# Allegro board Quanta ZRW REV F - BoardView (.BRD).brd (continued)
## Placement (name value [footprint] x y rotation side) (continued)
R257  *10k_4  [RC0402]  167.22 91.05 0 top
R258  75/f_6  [RC0603]  18.25 89.91 0 top
R259  ioac@10k_4  [RC0402]  46.32 87.75 0 top
R260  *ioac@100k/j_4  [RC0402]  48.35 87.75 0 top
R261  *15k_4  [RC0402]  41.11 87.24 180 top
R262  75/f_6  [RC0603]  18.25 86.99 0 top
R263  ioac@0_4  [RC0402]  45.68 86.61 0 top
R264  nac@0_4  [RC0402]  45.68 85.59 0 top
R265  *0_4  [RC0402]  175.09 85.11 0 top
R266  0_4  [RC0402]  210.91 85.57 0 top
R267  *0_4  [RC0402]  188.3 84.2 180 top
R268  *0_4  [RC0402]  175.09 84.1 0 top
R269  75/f_6  [RC0603]  18.25 83.94 0 top
R270  *0_4  [RC0402]  210.91 83.64 0 top
R271  *0_6  [RC0603]  170.52 83.05 90 top
R272  *0_6  [RC0603]  171.79 83.05 90 top
R273  *0_4  [RC0402]  175.09 82.83 0 top
R274  *0_4  [RC0402]  175.09 81.81 0 top
R275  *49.9k/f_4  [RC0402]  151.9 87.65 0 top
R276  *0/j_4  [RC0402]  36.92 81.4 90 top
R277  10k/f_4  [RC0402]  38.06 81.4 270 top
R278  *0_6  [RC0603]  171.92 80.89 0 top
R279  *0_4  [RC0402]  175.09 80.79 0 top
R280  *49.9k/f_4  [RC0402]  151.9 86.64 0 top
R281  *10k/f_4  [RC0402]  37.55 79.75 0 top
R282  *0_4  [RC0402]  175.22 79.5 0 top
R283  *49.9k/f_4  [RC0402]  158.97 79.37 180 top
R284  sp@0_4  [RC0402]  202.15 79.37 270 top
R285  *sp@0_4  [RC0402]  203.16 79.37 90 top
R286  *0_4  [RC0402]  204.18 79.37 270 top
R287  sp@0_4  [RC0402]  205.19 79.37 90 top
R288  *0_4  [RC0402]  206.21 79.37 90 top
R289  *0_6  [RC0603]  174.97 78.25 180 top
R290  *49.9k/f_4  [RC0402]  158.97 78.23 180 top
R291  *0_6  [RC0603]  174.97 76.98 180 top
R292  *4.7k_4  [RC0402]  22.82 76.45 90 top
R293  *4.7k_4  [RC0402]  23.84 76.45 90 top
R294  4.99k_4  [RC0402]  21.81 73.91 90 top
R295  *4.7k_4  [RC0402]  22.82 73.91 270 top
R296  *4.7k_4  [RC0402]  23.84 73.91 270 top
R297  4.7k_4  [RC0402]  24.85 73.91 90 top
R298  *4.7k_4  [RC0402]  25.87 73.91 90 top
R299  20k/f_4  [RC0402]  83.27 73.91 0 top
R300  20k/f_4  [RC0402]  85.31 73.91 180 top
R301  45.3k/f_4  [RC0402]  81.5 73.53 90 top
R302  *short_6  [SHORT0603]  93.56 73.02 270 top
R303  *120/f_4  [RC0402]  15.07 71.88 270 top
R304  1.5k/f_4  [RC0402]  81.5 71.5 90 top
R305  10k_4  [RC0402]  164.43 70.84 0 top
R306  *0_4  [RC0402]  29.68 70.48 180 top
R307  2/f_6  [RC0603]  93.87 70.38 90 top
R308  1k_4  [RC0402]  84.67 70.35 180 top
R309  1.8k/f_4  [RC0402]  95.47 70.33 270 top
R310  1.8k/f_4  [RC0402]  97.5 70.33 90 top
R311  *4.7k_4  [RC0402]  18.63 69.85 180 top
R312  *120/f_4  [RC0402]  15.07 69.59 270 top
R313  24.9/f_4  [RC0402]  94.3 68.45 0 top
R314  *120/f_4  [RC0402]  15.07 67.31 270 top
R315  *120/f_4  [RC0402]  15.07 64.89 270 top
R316  2.2k_4  [RC0402]  21.68 62.99 270 top
R317  2.2k_4  [RC0402]  22.69 62.99 270 top
R318  *shortgs@0_6  [SHORT0603]  204.81 62.73 90 top
R319  *2.2k_4  [RC0402]  29.55 62.61 180 top
R320  *4.7k_4  [RC0402]  23.71 62.23 90 top
R321  *4.7k_4  [RC0402]  24.73 62.23 270 top
R322  *2.2k_4  [RC0402]  29.55 61.46 180 top
R323  10k_4  [RC0402]  162.9 60.85 90 top
R324  *10k_4  [RC0402]  164 60.85 270 top
R325  24.9/f_4  [RC0402]  94.58 60.32 180 top
R326  *0_4  [RC0402]  223.99 59.46 180 top
R327  *short_6  [SHORT0603]  92.16 58.8 270 top
R328  2/f_6  [RC0603]  92.16 56 90 top
R329  *shortgs@0_4  [SHORT0402]  197.83 55.8 0 top
R330  1.8k/f_4  [RC0402]  93.31 55.75 270 top
R331  1.8k/f_4  [RC0402]  95.34 55.75 90 top
R332  10k_4  [RC0402]  162.01 55.34 90 top
R333  *4.7k_4  [RC0402]  197.83 54.61 0 top
R334  *4.7k_4  [RC0402]  199.48 52.57 0 top
R335  10k_4  [RC0402]  163.54 52.35 90 top
R336  *shortgs@0_4  [SHORT0402]  201 52.07 90 top
R337  *shortgs@0_4  [SHORT0402]  203.54 52.07 90 top
R338  *short_6  [SHORT0603]  36.92 51.3 270 top
R339  *short_8  [SHORT0805]  221.32 51.3 90 top
R340  *short_4  [SHORT0402]  24.09 50.54 0 top
R341  *short_4  [SHORT0402]  24.09 49.53 0 top
R342  *short_4  [SHORT0402]  22.57 48.26 0 top
R343  *100k_4  [RC0402]  29.81 48.13 0 top
R344  *0_4  [RC0402]  31.97 48.13 0 top
R345  *1m_6  [RC0603]  34.51 48 0 top
R346  1.8k/f_4  [RC0402]  142.79 47.75 0 top
R347  *10k_4  [RC0402]  162.85 47.62 0 top
R348  *short_4  [SHORT0402]  22.57 47.24 0 top
R349  33_4  [RC0402]  179.59 121.64 270 top
R350  0_4  [RC0402]  31.97 47.11 180 top
R351  *0_4  [RC0402]  224.37 46.99 180 top
R352  22k_4  [RC0402]  36.03 46.86 180 top
R353  *short_4  [SHORT0402]  22.57 46.22 0 top
R354  4.7k_4  [RC0402]  36.03 45.72 0 top
R355  *short_4  [SHORT0402]  22.57 45.21 0 top
R356  10k_4  [RC0402]  26.76 44.7 0 top
R357  24.9/f_4  [RC0402]  136.74 44.07 180 top
R358  1.8k/f_4  [RC0402]  141.06 44.07 0 top
R359  33_4  [RC0402]  38.82 43.94 180 top
R360  10k_4  [RC0402]  26.76 43.56 0 top
R361  *2.2_6  [RC0603]  209.66 43.25 90 top
R362  *short_6  [SHORT0603]  138.14 42.97 0 top
R363  2/f_6  [RC0603]  140.8 42.97 180 top
R364  100k_4  [RC0402]  24.22 42.41 90 top
R365  0_4  [RC0402]  26.25 41.91 270 top
R366  *0_4  [RC0402]  27.27 41.91 270 top
R367  *short_6  [SHORT0603]  40.35 41.4 270 top
R368  100k_4  [RC0402]  205.32 40.51 270 top
R369  *10k/j_4  [RC0402]  40.86 38.98 270 top
R370  22_4  [RC0402]  34.76 38.86 0 top
R371  *short_4  [SHORT0402]  36.92 38.86 180 top
R372  1k_4  [RC0402]  39.84 38.86 90 top
R373  *22_4  [RC0402]  207.99 38.6 180 top
R374  10k_4  [RC0402]  205.32 38.35 270 top
R375  *0_4  [RC0402]  26.38 37.33 0 top
R376  39k/f_4  [RC0402]  19.9 37.03 270 top
R377  20k/f_4  [RC0402]  20.92 37.03 90 top
R378  100k_4  [RC0402]  26.38 36.32 180 top
R379  ev@10k_4  [RC0402]  205.32 36.32 270 top
R380  100k_4  [RC0402]  207.23 35.81 180 top
R381  *short_4  [SHORT0402]  19.77 35.05 0 top
R382  ev@10k_4  [RC0402]  196.1 34.62 180 top
R383  200k_4  [RC0402]  26.89 34.54 270 top
R384  *short_4  [SHORT0402]  19.77 34.03 0 top
R385  *short_4  [SHORT0402]  19.14 32.76 0 top
R386  *short_4  [SHORT0402]  19.14 31.75 0 top
R387  *short_4  [SHORT0402]  19.14 30.6 0 top
R388  *short_6  [SHORT0603]  25.87 30.6 180 top
R389  100k_4  [RC0402]  208.19 30.77 90 top
R390  *10k/f_4  [RC0402]  42.13 29.97 180 top
R391  *short_6  [SHORT0603]  57.62 29.97 180 top
R392  *short_4  [SHORT0402]  19.14 29.59 0 top
R393  *0_4  [RC0402]  21.55 29.03 270 top
R394  *0_4  [RC0402]  23.18 29 270 top
R395  *29.4k/f_4  [RC0402]  42.13 28.95 180 top
R396  *0_4  [RC0402]  53.94 28.44 270 top
R397  100k_4  [RC0402]  29.93 28.06 270 top
R398  6.2k/f_4  [RC0402]  60.54 28.06 270 top
R399  *0_4  [RC0402]  15.07 26.67 270 top
R400  *0_4  [RC0402]  16.09 26.67 270 top
R401  *0_4  [RC0402]  35.52 26.46 270 top
R402  *short_4  [SHORT0402]  202.15 24.76 180 top
R403  *tdi@0_4  [RC0402]  201.13 23.24 0 top
R404  *short_6  [SHORT0603]  60.28 16.35 0 top
R405  *tdi@0_4  [RC0402]  201.13 21.97 180 top
R406  *short_6  [SHORT0603]  62.69 17.14 270 top
R407  2.2k/j_4  [RC0402]  18.45 20.38 90 top
R408  *short_4  [SHORT0402]  16.93 20.34 180 top
R409  2.2k_4  [RC0402]  207.07 20.14 90 top
R410  2.2k_4  [RC0402]  208.14 20.11 90 top
R411  *short_4  [SHORT0402]  203.42 19.68 90 top
R412  *short_4  [SHORT0402]  204.56 19.68 90 top
R413  *short_4  [SHORT0402]  58 18.54 90 top
R414  *short_6  [SHORT0603]  64.95 17.14 270 top
R415  10k_4  [RC0402]  203.42 17.52 270 top
R416  10k_4  [RC0402]  204.56 17.52 270 top
R417  *10k/j_4  [RC0402]  15.33 17.01 270 top
R418  4.7k_4  [RC0402]  19.52 17.01 270 top
R419  *short_6  [SHORT0603]  67.22 17.16 270 top
R420  62/f_4  [RC0402]  14.7 15.36 180 top
R421  4.7k_4  [RC0402]  18.96 14.22 270 top
R422  62/f_4  [RC0402]  15.1 13.7 90 top
R423  *10k/j_4  [RC0402]  16.12 13.7 270 top
R424  2.2k/j_4  [RC0402]  18.96 12.1 90 top
R425  *short_4  [SHORT0402]  17.31 11.71 180 top
R426  *1m_4  [RC0402]  59.27 11.55 270 top
R427  *1m_4  [RC0402]  60.41 11.55 270 top
R428  *1m_4  [RC0402]  67.4 11.55 270 top
R429  *1m_4  [RC0402]  68.54 11.55 270 top
R430  71.5/f_4  [RC0402]  67.4 9.52 90 top
R431  130/f_4  [RC0402]  68.54 9.52 90 top
R432  71.5/f_4  [RC0402]  59.27 9.39 90 top
R433  130/f_4  [RC0402]  60.41 9.39 90 top
R434  *short_6  [SHORT0603]  63.84 8.76 270 top
R435  *100k_4  [RC0402]  64.99 8.5 270 top
R436  *1m_4  [RC0402]  57.49 7.74 270 top
R437  *short_4  [SHORT0402]  67.02 5.84 180 top
R438  *short_4  [SHORT0402]  59.27 5.71 180 top
R439  *0_4  [RC0402]  67.02 4.82 0 top
R440  *0_4  [RC0402]  59.27 4.69 0 top
R441  33_4  [RC0402]  146.77 196.44 0 bottom
R442  *short_4  [SHORT0402]  143.6 193.42 90 bottom
R443  *0_4  [RC0402]  144.61 193.42 270 bottom
R444  *tsi@10k_4  [RC0402]  135.98 184.65 180 bottom
R445  ev@100/f_4  [RC0402]  199.86 190.75 0 bottom
R446  ev@100/f_4  [RC0402]  202.02 190.75 180 bottom
R447  *100k_4  [RC0402]  138.39 188.34 180 bottom
R448  *100k_4  [RC0402]  138.39 187.32 0 bottom
R449  *100k_4  [RC0402]  138.39 190.37 0 bottom
R450  *100k_4  [RC0402]  138.39 189.35 180 bottom
R451  ev@100/f_4  [RC0402]  199.86 189.35 0 bottom
R452  ev@100/f_4  [RC0402]  202.02 189.35 180 bottom
R453  ev@10k/f_4  [RC0402]  196.43 188.97 0 bottom
R455  ev@100/f_4  [RC0402]  199.86 188.21 0 bottom
R456  ev@100/f_4  [RC0402]  202.02 188.21 180 bottom
R457  33_4  [RC0402]  138.14 186.3 180 bottom
R458  ev@100/f_4  [RC0402]  200.88 186.94 0 bottom
R459  ev@100/f_4  [RC0402]  203.03 186.94 180 bottom
R460  33_4  [RC0402]  113.37 181.73 90 top
R461  ev@100/f_4  [RC0402]  200.88 185.8 0 bottom
R462  ev@100/f_4  [RC0402]  203.03 185.8 180 bottom
R463  100k_4  [RC0402]  196.1 35.68 180 top
R464  ev@243_4  [RC0402]  194.02 184.58 270 bottom
R465  1k_4  [RC0402]  155.16 184.15 0 bottom
R466  ev@1.33k/f_4  [RC0402]  203.16 181.35 270 bottom
R467  ev@1.33k/f_4  [RC0402]  168.11 180.18 270 bottom
R469  ev@1.33k/f_4  [RC0402]  203.54 178.43 180 bottom
R471  ev@243_4  [RC0402]  177.89 172.33 0 bottom
R472  ev@1.33k/f_4  [RC0402]  169.3 171.93 270 bottom
R473  ev@2.49k/f_4  [RC0402]  168.11 167.13 90 bottom
R478  *0_4  [RC0402]  165.87 164.56 90 bottom
R481  *200/f_4  [RC0402]  168.03 164.26 90 bottom
R485  10k_4  [RC0402]  164.93 161.67 0 bottom
R486  ev@243_4  [RC0402]  207.99 156.71 90 bottom
R487  ev@243_4  [RC0402]  219.8 156.59 90 bottom
R488  *1k_4  [RC0402]  161.89 155.06 0 bottom
R489  *10k/f_4  [RC0402]  164.82 148.88 270 bottom
R490  ev@10k/f_4  [RC0402]  165.96 148.88 90 bottom
R491  gt@4.99k/f_4  [RC0402]  208.08 147.79 180 bottom
R492  gt@4.99k/f_4  [RC0402]  203.87 147.77 180 bottom
R493  sp@30.1k/f_4  [RC0402]  205.96 147.77 0 bottom
R494  gm@4.99k/f_4  [RC0402]  208.08 146.77 0 bottom
R495  gm@4.99k/f_4  [RC0402]  203.87 146.76 0 bottom
R496  *sp@4.99k/f_4  [RC0402]  206.01 146.76 180 bottom
R497  *10k/f_4  [RC0402]  166.05 146.73 90 bottom
R498  *10k/f_4  [RC0402]  164.79 146.72 270 bottom
R499  *10k/f_4  [RC0402]  185.27 141.26 90 bottom
R500  *10k/f_4  [RC0402]  187.55 141.26 90 bottom
R501  ev@10k/f_4  [RC0402]  189.84 141.26 90 bottom
R502  ev@1.8k_4  [RC0402]  193.27 141.26 90 bottom
R503  ev@2.2k_4  [RC0402]  194.41 141.26 90 bottom
R504  ev@10k/f_4  [RC0402]  195.55 141.26 90 bottom
R505  ev@2.2k_4  [RC0402]  196.7 141.26 270 bottom
R506  *10k/f_4  [RC0402]  183.98 141.22 90 bottom
R507  sp@49.9k/f_4  [RC0402]  186.4 141.22 270 bottom
R508  gm@10k/f_4  [RC0402]  188.81 141.22 270 bottom
R509  *10k/f_4  [RC0402]  180.3 141.14 90 bottom
R510  ev@40.2k/f_4  [RC0402]  181.57 141.14 270 bottom
R511  ev@10k/f_4  [RC0402]  182.74 141.12 90 bottom
R512  2.7k/f_4  [RC0402]  125.82 140.46 270 bottom
R513  *1k_4  [RC0402]  121.12 140.33 0 bottom
R514  51_4  [RC0402]  123.02 140.08 90 bottom
R515  51_4  [RC0402]  124.04 140.08 90 bottom
R516  ev@10k/f_4  [RC0402]  190.97 139.47 90 bottom
R517  *short_4  [SHORT0402]  121.5 139.31 180 bottom
R518  ev@10k/f_4  [RC0402]  189.84 139.22 90 bottom
R519  gm@45.3k/f_4  [RC0402]  185.27 139.1 90 bottom
R520  gm@45.3k/f_4  [RC0402]  187.55 139.1 90 bottom
R521  ev@1.8k_4  [RC0402]  193.27 139.1 90 bottom
R522  ev@2.2k_4  [RC0402]  194.51 139.1 90 bottom
R523  ev@2.2k_4  [RC0402]  195.55 139.1 270 bottom
R524  ev@10k/f_4  [RC0402]  196.7 139.1 90 bottom
R525  ev@10k/f_4  [RC0402]  182.74 139.09 90 bottom
R526  gm@4.99k/f_4  [RC0402]  183.98 139.06 90 bottom
R527  *24.9k/f_4  [RC0402]  186.4 139.06 90 bottom
R528  *15k/f_4  [RC0402]  188.81 139.06 270 bottom
R529  1k_4  [RC0402]  119.04 143.1 0 bottom
R530  100/f_4  [RC0402]  117.51 143.49 90 bottom
R531  499/f_4  [RC0402]  112.33 133.07 180 bottom
R532  *100k_4  [RC0402]  115.4 137.79 270 bottom
R533  *100k_4  [RC0402]  116.42 137.79 90 bottom
R534  51_4  [RC0402]  120.74 137.79 90 bottom
R535  *51_4  [RC0402]  121.75 137.79 90 bottom
R536  1m_4  [RC0402]  134.45 137.79 270 bottom
R537  *51_4  [RC0402]  123.53 137.66 90 bottom
R538  51_4  [RC0402]  124.55 137.66 90 bottom
R539  *short_4  [SHORT0402]  125.56 137.66 90 bottom
R540  10k_4  [RC0402]  159.47 137.16 270 bottom
R541  10k_4  [RC0402]  158.84 139.19 180 bottom
R542  10k_4  [RC0402]  158.46 137.16 270 bottom
R543  10k_4  [RC0402]  155.92 141.73 270 bottom
R544  *10k_4  [RC0402]  111.26 131.93 180 bottom
R546  *0_4  [RC0402]  127.52 136.9 90 bottom
R548  1k_4  [RC0402]  112.81 129.51 270 bottom
R549  *short_4  [SHORT0402]  121.63 136.27 0 bottom
R550  *short_6  [SHORT0603]  148.17 136.65 270 bottom
R552  220_4  [RC0402]  113.75 138.68 270 bottom
R553  *0_4  [RC0402]  127.98 135.38 180 bottom
R554  10k_4  [RC0402]  112.81 131.54 90 bottom
R555  10k_4  [RC0402]  159.85 135.12 90 bottom
R556  *short_4  [SHORT0402]  160.87 135.12 270 bottom
R558  51_4  [RC0402]  120.74 134.74 90 bottom
R559  51_4  [RC0402]  121.75 134.74 90 bottom
R560  *short_4  [SHORT0402]  162.73 134.51 0 bottom
R561  10k_4  [RC0402]  167.35 133.85 0 bottom
R562  100/f_4  [RC0402]  160.11 131.69 90 bottom
R563  100k_4  [RC0402]  162.24 129.87 0 bottom
R564  100k_4  [RC0402]  163.79 131.95 90 bottom
R565  gt3@0_6  [RC0603]  107.96 131.67 0 bottom
R566  *10k_4  [RC0402]  161.51 131.69 270 bottom
R567  *short_4  [SHORT0402]  167.35 129.79 180 bottom
R568  10k_4  [RC0402]  172.07 127.02 270 bottom
R569  *10k_4  [RC0402]  163.92 129.54 270 bottom
R570  100k_4  [RC0402]  171.06 127.25 270 bottom
R571  *short_4  [SHORT0402]  167.35 128.77 180 bottom
R572  2.2k_4  [RC0402]  169.38 129.03 180 bottom
R573  *10k_4  [RC0402]  160.11 127.38 270 bottom
R574  *10k_4  [RC0402]  161.12 127.38 270 bottom
R575  *10k_4  [RC0402]  162.52 127.38 270 bottom
R576  2.2k_4  [RC0402]  169.38 127.76 180 bottom
R577  2.2k_4  [RC0402]  169.38 126.74 180 bottom
R578  2.2k_4  [RC0402]  166.2 125.09 180 bottom
R580  2.2k_4  [RC0402]  164.15 125.29 0 bottom
R582  2.2k_4  [RC0402]  167.73 124.58 270 bottom
R585  2.2k_4  [RC0402]  161 120.9 270 bottom
R586  *1k_4  [RC0402]  159.98 120.52 270 bottom
R587  1k_4  [RC0402]  163.44 116.73 90 bottom
R588  8m@15_4  [RC0402]  172.81 115.54 0 bottom
R589  8m4m@15_4  [RC0402]  175.6 115.67 180 bottom
R590  *10k_4  [RC0402]  164.05 115.19 180 bottom
R591  10k_4  [RC0402]  170.65 115.18 180 bottom
R592  10k_4  [RC0402]  162.01 115.19 0 bottom
R593  10k_4  [RC0402]  166.08 115.06 0 bottom
R594  *4m@33_4  [RC0402]  172.76 114.52 0 bottom
R595  10k_4  [RC0402]  166.08 114.04 0 bottom
R596  *4m@33_4  [RC0402]  174.94 114.02 90 bottom
R597  *1k_4  [RC0402]  175.96 114.02 90 bottom
R598  10k_4  [RC0402]  162.01 114.07 0 bottom
R599  *10k_4  [RC0402]  164.05 114.07 180 bottom
R600  *10k_4  [RC0402]  168.11 113.91 180 bottom
R601  2.2k_4  [RC0402]  11.52 113.66 90 bottom
R602  8m@0_4  [RC0402]  169.76 113.66 90 bottom
R603  *4m@0_4  [RC0402]  170.78 113.66 90 bottom
R604  *4m@33_4  [RC0402]  172.58 113.51 0 bottom
R605  10k_4  [RC0402]  166.08 112.9 0 bottom
R606  10k_4  [RC0402]  166.97 116.07 180 bottom
R607  *10k_4  [RC0402]  168.24 115.06 180 bottom
R608  *10k_4  [RC0402]  168.11 112.77 180 bottom
R609  10k_4  [RC0402]  68.03 110.1 270 top
R610  10k_4  [RC0402]  162.06 111.83 0 bottom
R611  *10k_4  [RC0402]  164.1 111.83 180 bottom
R612  10k_4  [RC0402]  166.18 111.76 0 bottom
R613  *10k_4  [RC0402]  168.21 111.76 180 bottom
R614  10k_4  [RC0402]  162.12 110.82 180 bottom
R615  *10k_4  [RC0402]  164.15 110.82 180 bottom
R616  200/f_4  [RC0402]  166.2 110.74 0 bottom
R617  *0_4  [RC0402]  168.24 110.74 180 bottom
R618  10k_4  [RC0402]  162.27 109.72 180 bottom
R619  *1k_4  [RC0402]  164.99 109.72 180 bottom
R620  2.2k_4  [RC0402]  11.52 109.22 90 bottom
R621  *10k_4  [RC0402]  112.36 108.4 0 bottom
R622  *0_4  [RC0402]  168.11 108.78 0 bottom
R623  22/j_4  [RC0402]  162.01 108.71 0 bottom
R624  *20k_4  [RC0402]  164.05 108.71 180 bottom
R625  *1k_4  [RC0402]  166.08 108.71 0 bottom
R626  22/j_4  [RC0402]  164.05 107.69 0 bottom
R627  22/j_4  [RC0402]  166.08 107.69 0 bottom
R628  8.2k/f_4  [RC0402]  169.25 106.88 0 bottom
R629  10k_4  [RC0402]  166.08 106.68 0 bottom
R630  8.2k/f_4  [RC0402]  160.97 106.55 0 bottom
R631  *10k_4  [RC0402]  164.05 106.55 180 bottom
R632  gt3@0_4  [RC0402]  89.75 103.37 180 bottom
R633  gt3@0_4  [RC0402]  89.75 104.39 180 bottom
R634  gt3@0_4  [RC0402]  87.72 104.39 0 bottom
R635  49.9/f_4  [RC0402]  167.73 105.41 0 bottom
R636  gt3@0_4  [RC0402]  87.72 103.37 0 bottom
R637  *short_6  [SHORT0603]  17.69 104.62 0 bottom
R639  10k_4  [RC0402]  156.68 104.52 270 bottom
R640  *short_4  [SHORT0402]  157.82 104.52 270 bottom
R641  *4m@33_4  [RC0402]  177.63 104.52 270 bottom
R642  10k_4  [RC0402]  153.63 104.39 90 bottom
R643  *0_4  [RC0402]  152.62 104.34 270 bottom
R644  33_4  [RC0402]  147.15 104.26 270 bottom
R645  33_4  [RC0402]  148.17 104.01 270 bottom
R646  49.9/f_4  [RC0402]  167.88 103.88 90 bottom
R647  *short_4  [SHORT0402]  150.58 103.63 270 bottom
R648  10k_4  [RC0402]  151.6 103.63 270 bottom
R649  1k_4  [RC0402]  170.9 102.87 90 bottom
R650  8m4m@15_4  [RC0402]  169.51 102.74 90 bottom
R651  8.2k/f_4  [RC0402]  155.16 102.48 90 bottom
R652  *short_4  [SHORT0402]  156.68 102.48 90 bottom
R653  *short_4  [SHORT0402]  157.82 102.48 270 bottom
R654  8m@15_4  [RC0402]  177.63 102.48 90 bottom
R655  *short_4  [SHORT0402]  153.63 102.23 90 bottom
R657  *short_8  [SHORT0805]  226.91 101.09 0 bottom
R658  *4m@33_4  [RC0402]  177.76 100.86 180 bottom
R659  *short_4  [SHORT0402]  157.82 100.5 270 bottom
R660  33_4  [RC0402]  149.95 100.2 270 bottom
R661  *short_4  [SHORT0402]  152.49 100.2 90 bottom
R667  33_4  [RC0402]  148.3 99.56 0 bottom
R668  *short_4  [SHORT0402]  167.22 99.41 270 bottom
R669  *4m@33_4  [RC0402]  177.38 99.31 180 bottom
R670  *short_4  [SHORT0402]  154.39 98.42 0 bottom
R671  nac@0_4  [RC0402]  191.86 98.17 0 bottom
R672  nac@0_8  [RC0805]  222.31 98.04 90 bottom
R673  ioac@22_8  [RC0805]  224.32 98.04 90 bottom
R674  *0_4  [RC0402]  151.85 97.91 90 bottom
R675  100k_4  [RC0402]  152.87 97.91 270 bottom
R676  *short_4  [SHORT0402]  156.55 97.84 90 bottom
R677  *short_4  [SHORT0402]  157.57 97.84 90 bottom
R678  80.6/f_4  [RC0402]  166.33 98.01 0 bottom
R679  470_4  [RC0402]  154.39 97.4 0 bottom
R680  ioac@0_4  [RC0402]  191.86 97.15 0 bottom
R681  100/f_4  [RC0402]  166.33 97 0 bottom
R682  *100k_4  [RC0402]  99.66 96.64 90 bottom
R683  *0_6  [RC0603]  164.1 95.86 180 bottom
R684  8m4m@15_4  [RC0402]  177.38 96.01 0 bottom
R685  120/f_4  [RC0402]  166.61 95.83 0 bottom
R686  ioac@100k  [RC0402]  216.24 95.5 0 bottom
R687  8m@15_4  [RC0402]  177.38 94.99 0 bottom
R688  *short_4  [SHORT0402]  191.86 94.1 180 bottom
R689  *4m@33_4  [RC0402]  177.38 93.98 180 bottom
R690  *short_4  [SHORT0402]  191.86 93.09 180 bottom
R691  8m4m@15_4  [RC0402]  177.51 92.96 180 bottom
R692  *ioac@100k  [RC0402]  215.86 92.32 0 bottom
R693  *short_4  [SHORT0402]  191.86 92.07 180 bottom
R694  *0_4  [RC0402]  177.51 91.82 0 bottom
R695  ioac@100k  [RC0402]  222.59 91.82 0 bottom
R696  *short_4  [SHORT0402]  191.99 91.05 180 bottom
R697  gt3@10k_4  [RC0402]  58.89 90.8 270 bottom
R698  1k_4  [RC0402]  171.67 90.8 0 bottom
R699  *0_4  [RC0402]  177.51 90.8 0 bottom
R700  *short_6  [SHORT0603]  169 89.78 0 bottom
R701  2.49k/f_4  [RC0402]  34.25 89.66 0 bottom
R702  ioac@10k/f_4  [RC0402]  45.55 89.66 180 bottom
R703  *ioac@0_4  [RC0402]  215.23 89.66 90 bottom
R704  ioac@0_4  [RC0402]  216.37 89.66 90 bottom
R705  gt3@10k_4  [RC0402]  54.83 88.77 270 bottom
R706  *10k_4  [RC0402]  55.84 88.77 90 bottom
R707  gt3@10k_4  [RC0402]  56.86 88.77 90 bottom
R708  *10k_4  [RC0402]  57.87 88.77 270 bottom
R709  nac@0/j_4  [RC0402]  48.6 88.26 90 bottom
R710  *ioac@10k_4  [RC0402]  178.14 87.63 270 bottom
R711  1k_4  [RC0402]  41.11 87.24 0 bottom
R712  **ioac@100k/j_4  [RC0402]  175.86 86.74 180 bottom
R713  nac@0_4  [RC0402]  49.24 86.74 180 bottom
R714  *10k_4  [RC0402]  194.27 86.23 0 bottom
R715  ioac@0_4  [RC0402]  49.24 85.72 180 bottom
R716  **10k_4  [RC0402]  193.76 82.67 0 bottom
R717  *10k_4  [RC0402]  218.53 77.08 180 bottom
R718  *0_4  [RC0402]  19.75 76.5 270 bottom
R719  100k_4  [RC0402]  211.8 75.81 0 bottom
R720  20k_4  [RC0402]  14.19 75.69 0 bottom
R721  0_4  [RC0402]  14.19 74.67 0 bottom
R722  *1m_4  [RC0402]  14.19 73.66 180 bottom
R723  tpm_i@0_6  [RC0603]  214.85 61.21 0 bottom
R724  *4.7k_4  [RC0402]  214.85 59.94 180 bottom
R725  tpm_n@0_6  [RC0603]  211.42 59.43 0 bottom
R726  tpm_i@0_4  [RC0402]  218.53 59.05 0 bottom
R727  tpm_i@4.7k_4  [RC0402]  214.59 58.42 90 bottom
R728  tpm_i@0_4  [RC0402]  215.73 58.42 90 bottom
R729  *10k_4  [RC0402]  216.88 58.42 90 bottom
R730  10k_4  [RC0402]  197.45 51.81 270 bottom
R731  4.7k_4  [RC0402]  198.59 51.81 270 bottom
R732  4.7k_4  [RC0402]  199.73 51.81 270 bottom
R733  2.2k_4  [RC0402]  200.88 51.81 270 bottom
R734  2.2k_4  [RC0402]  201.89 51.81 270 bottom
R735  *10k_4  [RC0402]  194.91 49.14 270 bottom
R736  *10k_4  [RC0402]  196.05 49.14 270 bottom
R737  1k_4  [RC0402]  198.46 49.14 270 bottom
R738  43_4  [RC0402]  201.79 49.14 270 bottom
R739  100k_4  [RC0402]  202.91 49.14 270 bottom
R740  ev@10k_4  [RC0402]  205.19 49.14 270 bottom
R741  10k_4  [RC0402]  193.64 49.02 270 bottom
R742  *short_4  [SHORT0402]  218.78 46.6 90 bottom
R743  tpm_n@0_4  [RC0402]  219.93 46.6 90 bottom
R744  *4.7k_4  [RC0402]  211.14 45.97 270 bottom
R745  *shorttpm@0_6  [SHORT0603]  212.43 45.72 270 bottom
R746  33_4  [RC0402]  227.8 112.14 0 top
R747  2.2_6  [RC0603]  188.81 44.7 90 bottom
R748  *0_4  [RC0402]  210.02 35.05 90 bottom
R749  *short_4  [SHORT0402]  211.7 34.51 180 bottom
R750  *short_4  [SHORT0402]  32.73 31.36 90 bottom
R751  33_4  [RC0402]  142.46 191.26 90 bottom
R752  *short_6  [SHORT0603]  203.29 26.16 90 bottom
R753  10k_4  [RC0402]  193.26 23.36 180 bottom
R754  *0_4  [RC0402]  208.88 23.11 0 bottom
R755  *0_4  [RC0402]  213.3 18.26 270 bottom
R756  *0_4  [RC0402]  216.5 77.59 0 bottom
R757  *0_4  [RC0402]  216.5 76.58 0 bottom
R758  *ev@0_4  [RC0402]  196.56 145.54 90 top
R759  *short_4  [SHORT0402]  160.01 110.89 90 bottom
R760  *short_4  [SHORT0402]  110.93 109.57 180 bottom
R761  100k_4  [RC0402]  110.96 137.16 0 bottom
R762  *gt3@0_4  [RC0402]  93.56 111.5 0 bottom
R764  10k_4  [RC0402]  160.87 116.53 0 top
R765  *10k_4  [RC0402]  163.39 118.21 270 top
R766  10k_4  [RC0402]  161.86 112.98 0 bottom
R767  *10k_4  [RC0402]  164.05 112.98 180 bottom
R768  *60.4/f_4  [RC0402]  126.23 140.81 180 top
R769  *33_4  [RC0402]  166.97 131.19 0 bottom
R770  *33_4  [RC0402]  166.97 132.2 0 bottom
R771  *0_4  [RC0402]  208.25 92.06 0 top
R772  *0_4  [RC0402]  210.52 85.18 270 top
R774  33_4  [RC0402]  191.86 96.13 0 bottom
R775  *0_4  [RC0402]  162.9 118.28 0 bottom
R776  33_4  [RC0402]  143.65 16.15 270 bottom
R777  *0_4  [RC0402]  197.47 85.82 270 top
R778  1k_4  [RC0402]  164 112.34 0 top
R779  2.2_6  [RC0603]  209.88 40.62 270 top
R780  20k/f_4  [RC0402]  169.87 131.33 270 bottom
R781  20k/f_4  [RC0402]  168.83 130.82 90 bottom
R782  0_4  [RC0402]  196.35 49.06 270 top
R783  *0_4  [RC0402]  188.73 42.34 270 bottom
R784  *0_4  [RC0402]  208.75 45.79 180 bottom
R785  *0_4  [RC0402]  210.53 33.5 180 bottom
R786  100k_4  [RC0402]  172.25 43.51 270 top
R787  *0_4  [RC0402]  214.31 17.95 90 bottom
R788  49.9/f_4  [RC0402]  119.04 142.08 0 bottom
R789  0_6  [RC0603]  163.41 97.02 180 bottom
R790  *0_4  [RC0402]  221.58 24.76 180 top
R791  0_4  [RC0402]  51.14 11.32 0 top
R792  *0_4  [RC0402]  51.14 15.19 0 top
R793  gt3@0_8  [RC0805]  65.49 96.26 180 bottom
R794  gt3@0_8  [RC0805]  65.49 93.72 180 bottom
R795  0_4  [RC0402]  124.8 142.13 270 bottom
R796  0_4  [RC0402]  123.02 142.13 270 bottom
R797  0_4  [RC0402]  121.17 141.9 270 bottom
RP1  *10k_10p8r  [10P8R]  196.76 27.96 90 top
SPAD1  *spad-zrz-1np  [SPAD-ZRZ-1NP]  14.21 28.93 180 top
SPAD2  *spad-zrz-1np  [SPAD-ZRZ-1NP]  18.75 35.56 90 top
SPAD3  *spad-zrz-1np  [SPAD-ZRZ-1NP]  23.05 51.18 90 top
SPAD4  *spad-zrz-1np  [SPAD-ZRZ-1NP]  23.05 48.89 90 top
SPAD5  *spad-zrz-1np  [SPAD-ZRZ-1NP]  14.39 48.48 180 top
SPAD6  *spad-zrz-1np  [SPAD-ZRZ-1NP]  21.2 44.75 90 top
SPAD7  *spad-zrz-1np  [SPAD-ZRZ-1NP]  21.27 46.73 90 top
SPAD8  *spad-zrz-1np  [SPAD-ZRZ-1NP]  14.39 46.73 180 top
SPAD9  *spad-zrz-1np  [SPAD-ZRZ-1NP]  18.28 31.11 90 top
SPAD10  *spad-zrz-1np  [SPAD-ZRZ-1NP]  14.21 30.76 180 top
SPAD11  *spad-zrz-1np  [SPAD-ZRZ-1NP]  18.28 29.08 90 top
SPAD12  *spad-zrz-1np  [SPAD-ZRZ-1NP]  18.75 33.52 90 top
SW1  power_sw  [SW-TME-533B-Q-TR-6P]  211.39 81.4 180 bottom
SW2  power_sw  [SW-TME-533B-Q-TR-6P]  194.65 16.89 270 bottom
TP2  *  [TP2050]  192.09 162.61 0 top
TP3  *  [TP2050]  188.72 155.86 270 top
TP4  *  [TP2050]  191.76 154.83 270 top
TP5  *  [TP2050]  190.39 155.06 0 top
TP6  *  [TP2675]  190.21 153.46 270 top
TP7  *  [TP2675]  192.19 152.52 270 top
TP8  *  [TP2050]  181.09 152.32 0 top
TP9  *  [TP2050]  185.13 151.68 0 top
TP10  *  [TP2050]  182.54 151.28 0 top
TP11  *  [TP2050]  187.44 150.54 0 top
TP12  *  [TP2650]  137.58 126.18 0 top
TP14  *  [TP2650]  145 115.95 0 top
TP15  *pad  [TP2675]  23.2 115.31 0 top
TP16  *  [TP2675]  149.24 114.45 0 top
TP17  *  [TP2650]  142.56 113.13 0 top
TP18  *pad  [TP2675]  132.88 113.09 0 top
TP19  *  [TP2675]  154.51 112.15 0 top
TP20  *  [TP2650]  139.53 110.54 0 top
TP21  *pad  [TP2675]  127.47 109.72 0 top
TP22  *  [TP2650]  166.15 108.45 0 top
TP23  *pad  [TP2675]  146.65 108.38 0 top
TP24  *pad  [TP2675]  26.12 107.95 0 top
TP25  *  [TP2650]  169 103.88 0 top
TP26  *  [TP2650]  38.32 97.53 180 top
TP27  *  [TP2650]  41.47 97.38 180 top
TP28  *  [TP2650]  39.84 97.02 180 top
TP29  *pad  [TP2675]  166.26 99.36 180 bottom
TP30  *pad  [TP2675]  155.54 96.39 0 top
TP31  *  [TP2675]  163.16 96.39 0 top
TP33  *pad  [TP2675]  192.87 38.2 0 top
TP34  *  [TP2650]  37 37.33 0 top
TP35  *  [TP2650]  61.81 23.74 90 top
TP36  *  [TP2650]  53.3 22.6 90 top
TP37  *  [TP2650]  62.7 22.6 90 top
TP38  *  [TP2650]  53.43 21.33 90 top
TP39  *  [TP2650]  61.81 21.2 90 top
TP40  *  [TP2650]  56.73 19.43 90 top
TP41  *  [TP2650]  59.07 19.02 90 top
TP42  *  [TP2650]  58.1 16.66 90 top
TP43  *  [TP2650]  52.03 16.76 90 top
TP45  *  [TP2050]  167.32 149.81 90 bottom
TP46  *  [TP2050]  167.42 148.13 90 bottom
TP47  *  [TP2050]  167.12 146.86 90 bottom
TP48  *  [TP2050]  166.45 145.01 90 bottom
TP49  *  [TP2050]  167.75 144.98 180 bottom
TP50  *  [TP2050]  179.36 143.38 180 bottom
TP51  *  [TP2050]  182.05 143.35 180 bottom
TP52  *  [TP2050]  183.43 143.35 180 bottom
TP53  *  [TP2050]  176.67 142.59 180 bottom
TP54  *  [TP2050]  178.07 142.57 180 bottom
TP55  *  [TP2050]  180.56 142.62 180 bottom
TP56  *  [TP2050]  170.65 142.49 180 bottom
TP57  *  [TP2050]  171.92 142.49 180 bottom
TP58  *  [TP2050]  190.97 142.44 90 bottom
TP59  *  [TP2050]  179.25 142.08 180 bottom
TP60  *  [TP2050]  177.36 141.5 180 bottom
TP61  *  [TP2050]  176.19 140.92 180 bottom
TP62  *  [TP2650]  124.27 136.17 180 bottom
TP63  *  [TP2675]  158.79 134.77 180 bottom
TP64  *  [TP2650]  126.28 134.87 180 bottom
TP65  *  [TP2650]  119.29 134.9 180 bottom
TP66  *  [TP2675]  160.64 130.07 180 bottom
TP67  *  [TP2675]  162.52 132.33 180 bottom
TP68  *  [TP2675]  162.17 128.93 180 bottom
TP73  *  [TP2650]  160.64 109.47 180 bottom
TP74  *pad  [TP2675]  167.78 106.96 180 bottom
TP75  *  [TP2650]  7.81 106.32 180 bottom
TP76  *  [TP2675]  196.3 66.16 180 bottom
TP77  *  [TP2650]  206.16 51.25 180 bottom
TP78  *pad  [TP2675]  204.69 47.62 180 bottom
TP84  *  [TP2675]  146.6 115.95 0 top
TP86  *  [TP2650]  125.44 117.34 0 top
TP87  *  [TP2650]  124.17 116.96 0 top
TP88  *  [TP2675]  116.6 120.72 0 top
TP89  *  [TP2650]  126.58 137.05 180 bottom
TP90  *  [TP2650]  126.96 138.38 180 bottom
TP91  *  [TP2650]  125.54 136.22 180 bottom
TP92  *  [TP2650]  119.11 137.08 180 bottom
TP93  *  [TP2650]  129.12 143.18 180 bottom
TP94  *  [TP2650]  129.12 141.91 180 bottom
TP95  *  [TP2675]  151.57 116.38 0 top
U1  g5243at11u  [SOT23-2_8-95-6P]  117.34 184.53 90 top
U2  dr@vram _ddr3_samsung_256mx16  [BGA96-HYNIX-H5TQ1G63AFP]  174.74 181.5 90 top
U3  dr@vram _ddr3_samsung_256mx16  [BGA96-HYNIX-H5TQ1G63AFP]  186.61 181.5 90 top
U4  dr@vram _ddr3_samsung_256mx16  [BGA96-HYNIX-H5TQ1G63AFP]  203.67 166.62 90 top
U5  dr@vram _ddr3_samsung_256mx16  [BGA96-HYNIX-H5TQ1G63AFP]  215.54 166.62 90 top
U6  74aup1g07gw  [SOT353-1-2_125-65-5P]  196.8 89.12 270 top
U7  gt@mc74vhc1g08dft2g  [SSOP5-P-A-TOSHIBA-B]  194.02 137.38 90 top
U8  *tc7sh08fu  [SSOP5-P-A-TOSHIBA-B]  160.36 135.64 270 top
U9  gt@nl17sz32dft2g  [SSOP5-P-A-TOSHIBA-B]  173.84 134.27 0 top
U10  ev@mc74vhc1g08dft2g  [SSOP5-P-A-TOSHIBA-B]  174.46 131.44 180 top
U12  g991p11u  [SOIC8-6-1_27]  50 109.6 90 top
U13  it6515fn_qfn-40  [QFN40-5X5-4-41P-IT6515FN]  21.93 108.58 270 top
U14  tc7sh08fu  [SSOP5-P-A-TOSHIBA-B]  171.08 106.68 270 top
U15  rtl8111h-cg  [QFN32-4X4-4-33P-0_9H]  35.9 87.12 270 top
U16  *nsm0410dt  [MIC-FM-M201-U03-6P]  81.89 85.9 270 top
U17  spm0437hd4h-b  [MIC-FM-M201-U03-6P]  203.91 85.89 90 top
U18  ps8201atqfn40gtr2-a0  [QFN40-5X5-4-50P-0_75H]  24.09 68.19 90 top
U19  gs@lis3dhtr  [SENSOR-3X3-5-16P-SMT]  203.06 57.3 270 top
U20  g524b2t11u  [SOT23-5]  23.84 55.88 270 top
U21  usb30_esd_az1065-06f.r7g  [ESD10-4_1X2-8-11P]  17.74 47.49 270 top
U22  tps2544rter  [QFN16-3X3-5-17P-TPS2543RTER]  20.66 41.4 90 top
U23  alc255  [QFN48-6X6-4-49P-ALC280]  32.6 33.9 180 top
U24  usb30_esd_az1065-06f.r7g  [ESD10-4_1X2-8-11P]  15.96 30.98 270 top
U25  *g923-330t1uf  [SOT23-5]  45.55 29.08 0 top
U26  rts5170  [QFN24-4X4-5-25P-ALC5629]  57.75 22.98 180 top
U28  ev@vram _ddr3_samsung_256mx16  [BGA96-HYNIX-H5TQ1G63AFP]  174.74 181.5 90 bottom
U29  ev@vram _ddr3_samsung_256mx16  [BGA96-HYNIX-H5TQ1G63AFP]  186.61 181.5 90 bottom
U31  ev@vram _ddr3_samsung_256mx16  [BGA96-HYNIX-H5TQ1G63AFP]  203.67 166.62 90 bottom
U32  ev@vram _ddr3_samsung_256mx16  [BGA96-HYNIX-H5TQ1G63AFP]  215.54 166.62 90 bottom
U33  74aup1g07gw  [SOT353-1-2_125-65-5P]  164.05 164.59 90 bottom
U34  ev@n15s_gt  [BGA595-NVIDIA-N13P-GV2-S-A2]  182.33 157.22 180 bottom
U35  skl_ult/bga  [BGA1356-INTEL-SKYLAKE-U]  136.5 119.63 270 bottom
U36  *rclamp0524p  [SLP10-2_5X1-5-10P]  8.17 113.08 90 bottom
U37  m74vhc1gt125df2g  [SSOP5-P-A-TOSHIBA-B]  16.22 111.12 270 bottom
U38  *rclamp0524p  [SLP10-2_5X1-5-10P]  8.06 109.42 90 bottom
U39  *4m@rom-4m_ec  [SOIC8-7_9-1_27]  174.21 107.95 0 bottom
U40  m74vhc1gt125df2g  [SSOP5-P-A-TOSHIBA-B]  13.58 107.49 270 bottom
U41  w25q64fv  -- 8mb  [SOIC8-8-1_27]  171.67 96.52 0 bottom
U42  transformer  [TRF-N1010G-25P]  22.45 87.46 270 bottom
U43  *74aup1g07gw  [SOT353-1-2_125-65-5P]  193.51 84.45 180 bottom
U44  tpm@npct650  [TSSOP28-6_4-65-SLB9635TT]  215.73 52.32 0 bottom
U45  it8987/cx  [LQFP128-16X16-4-1_6H]  200.11 37.71 270 bottom
U46  g524b2t11u  [SOT23-5]  210.63 25.9 270 bottom
U47  tc7sh08fu  [SSOP5-P-A-TOSHIBA-B]  195.52 85.09 90 top
U48  tc7sh08fu  [SSOP5-P-A-TOSHIBA-B]  222.08 22.73 0 top
U49  *tc7sh08fu  [SSOP5-P-A-TOSHIBA-B]  51.65 9.39 180 top
U50  tc7sh08fu  [SSOP5-P-A-TOSHIBA-B]  51.65 13.25 180 top
Y1  25mhz +-30ppm  [XTL-3_2X2_5-2_2X1_7]  35.78 94.23 0 top
Y2  32.768khz  [XTL-3_2X1_5-2_5-0_8H]  159.85 92.32 270 top
Y3  ev@27mhz +-10ppm  [XTL-3_2X2_5-2_2X1_7]  200.63 147.86 180 bottom
Y4  24mhz  [XTL-3_2X2_5-2_2X1_7-4P]  130.64 138.17 180 bottom

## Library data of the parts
BT1 = BAT-AP-AAA-BAT-054-K01-2P-SMT
C2 C4 C8-C20 C22-C25 C27 C28 C31 C33-C35 C37-C39 C41-C46 C48 C51 C53 C56-C58 C60-C62 C66-C68 C70 C71 C76 C77 C81 C82 C88 C89 C91 C92 C96-C108 C114 C115 C117 C119 C121 C122 C124 C125 C127-C131 C133 C134 C136 C139 C141 C147 C148 C151 C155-C158 C161 C162 C164-C168 C170 C172-C177 C179 C180 C185 C186 C191 C192 C217 C218 C221 C223 C225 C229 C230 C232 C238 C247 C250 C254 C256-C259 C261 C263 C265 C268 C270 C279-C281 C283 C284 C286 C288 C290-C292 C300 C301 C304-C306 C309 C314-C320 C322-C339 C341 C343-C346 C348-C360 C362-C364 C367-C387 C389-C391 C393 C395-C400 C403 C405-C411 C413 C415 C416 C421 C422 C424-C429 C431 C434-C437 C440-C442 C444 C446-C448 C450 C451 C453 C454 C456 C458-C462 C464-C469 C474-C485 C488-C502 C504 C505 C507-C511 C513 C514 C517-C520 C522 C524-C530 C532-C541 C543-C548 C550 C551 C553-C555 C557 C558 C561-C567 C569-C573 C575-C581 C583 C585 C586 C588 C590 C592-C595 C597-C600 C604 C606-C624 C626-C629 C632-C639 C641-C644 C647-C649 C651-C658 C660-C665 C667-C669 C672-C680 C682 C686 C687 C695 C698 C700 C701 C708-C714 C716-C722 C724-C733 C735 C736 C738 C739 C741-C745 C747-C751 C753-C764 C766 C768-C775 C777-C781 C783 C785-C788 C791-C794 C796-C819 D2-D5 D24-D27 PC1 PC3 PC6-PC12 PC14-PC46 PC55-PC58 PC67 PC79 PC89 PC92-PC96 PC100 PC101 PC103 PC109 PC113 PC123 PC125 PC129-PC135 PC139 PC159-PC161 PC171 PC174 PC175 PC177 PC178 PC193-PC195 PC199 PC208 PC214 PC219 PC226 PC229 PC230 PC233 PC237-PC242 PC244 PC246-PC248 PC252 PC265 PC271 PC282 PC6100 PC6214 PC6218 PC6228 = CC0402
C7 C29 C30 C83 C144 C150 C153 C159 C182 C190 C199 C248 C645 C650 C659 C666 C690 C696 C697 C699 C702 PC47 PC49 PC52 PC54 PC68 PC69 PC99 PC118 PC120 PC127 PC148 PC152 PC155 PC157 PC164-PC170 PC172 PC179-PC182 PC186 PC187 PC202 PC205 PC207 PC209 PC211 PC228 PC245 PC6216 PC6220 = CC0805
C21 C26 C32 C36 C40 C47 C49 C50 C52 C54 C55 C59 C63-C65 C69 C72-C75 C78-C80 C86 C87 C90 C93-C95 C109-C113 C116 C118 C120 C123 C126 C132 C135 C137 C138 C140 C142 C143 C145 C146 C149 C152 C154 C160 C163 C169 C171 C178 C187 C202 C203 C210 C219 C224 C226 C233 C236 C243 C251 C255 C272-C277 C282 C289 C302 C303 C307 C310 C321 C340 C342 C347 C361 C365 C366 C388 C392 C394 C401 C402 C404 C412 C414 C417-C420 C423 C430 C432 C438 C439 C443 C445 C449 C455 C463 C470-C473 C515 C516 C523 C531 C542 C549 C552 C556 C559 C560 C568 C574 C582 C584 C587 C596 C601-C603 C605 C625 C630 C631 C691-C694 C703-C707 C715 C723 C734 C737 C752 C765 C767 C776 C789 C790 PC2 PC4 PC5 PC13 PC48 PC50 PC51 PC53 PC62 PC64-PC66 PC72 PC73 PC81 PC82 PC102 PC104 PC115-PC117 PC119 PC121 PC122 PC124 PC126 PC128 PC136 PC140-PC147 PC149-PC151 PC153 PC154 PC156 PC173 PC176 PC183 PC184 PC191 PC196 PC200 PC203 PC204 PC206 PC213 PC222 PC223 PC225 PC231 PC232 PC234-PC236 PC243 PC249 PC250 PC259 PC261 PC268 PC278 PC6097-PC6099 PC6209 PC6211 PC6213 PC6215 PC6219 PC6221 PC6222 PC6225 PC6226 PC6230 PC6231 = CC0603
C84 D23 D28 D34 L5-L7 L13 L18 PR2 PR17 PR19 PR20 PR57-PR60 PR65 PR67 PR68 PR76 PR107 PR108 PR122 PR140-PR143 PR147 PR152 PR155 PR182-PR184 PR186 PR189 PR190 PR204 PR214 PR215 PR221 PR222 PR250 PR291 PR294 PR306 PR308 PR312 PR313 PR334-PR337 PR6286-PR6289 R72 R203 R210 R251 R258 R262 R269 R271 R272 R278 R289 R291 R307 R328 R345 R361 R363 R565 R683 R723 R725 R747 R779 R789 = RC0603
C85 C457 C740 = CC3528
C181 C184 C188 C189 C193-C198 C200 C201 C204-C207 C209 C212 C214-C216 C222 C227 C228 C235 C237 C239-C242 C245 C246 C249 C252 C260 C262 C264 C266 C267 C269 C278 C285 C297-C299 C308 C311-C313 C681 C683-C685 C688 C689 = CC0201
C433 C486 PC59 PC60 PC158 PC162 PC163 PC189 = CC7343
C452 C487 C782 = CC1206
C670 C671 PR12 PR25-PR30 PR32 PR33 PR38 PR42 PR43 PR46 PR47 PR50 PR52 PR61 PR62 PR73 PR110 PR116 PR123 PR128 PR129 PR134 PR160 PR167 PR170-PR172 PR175-PR178 PR181 PR191 PR209 PR210 PR228 PR229 PR233 PR234 PR237-PR240 PR244-PR246 PR252 PR254 PR260 PR301 PR305 PR307 PR311 PR328 PR332 PR333 PR343 PR6278 PR6283 R1 R2 R37 R66 R67 R119 R171 R175 R194 R224 R229 R235 R329 R336 R337 R340-R342 R348 R353 R355 R371 R381 R384-R387 R392 R402 R408 R411-R413 R425 R437 R438 R442 R517 R539 R549 R556 R560 R567 R571 R640 R647 R652 R653 R655 R659 R661 R668 R670 R676 R677 R688 R690 R693 R696 R742 R749 R750 R759 R760 = SHORT0402
C746 = CC1808
CN2 = 88511-180N-18P-L
CN3 = 88513-0601-6P-L-SMT
CN4 = SDCARD-PSDAT4-09GLBS1NN4H0-11P
CN5 = GS12401-1011-40P-R-NH-SMT
CN6 = 50503-0040N-V01-4P-L
CN7 = DSUB-070546FR015S265ZR-15P-V
CN8 = HS8803F-3P-L
CN9 = SATA-SLS-13PVAB-13P-R
CN10 = NGFF-APCI0085-P005A-75P-KE
CN11 = RJ45-130452-01-8P-RUV
CN12 = HDMI-10444-19001-19P
CN13 CN16 = USB-2UB4029-200201F-9P-SMT
CN14 = SATA-C166FQ-12208-L-22P-R
CN17 = 88513-0801-8P-L
CN18 = 50224-00401-001-4P-L
CN20 = 50584-0280N-V01-28P-L
CN21 = PHJK-2SJ3080-077111F-6P
CN22 = 88511-10XX-10P-L
CP1-CP6 = 8P4R
D1 D8-D11 D14-D20 D30 D31 D35 PD1 PD2 PD4 = DSM
D6 L1-L4 L11 L12 L20-L22 PR1 PR3 PR4 PR6-PR11 PR13-PR16 PR18 PR21-PR24 PR31 PR34-PR36 PR39-PR41 PR44 PR45 PR48 PR49 PR51 PR63 PR64 PR66 PR71 PR72 PR74 PR75 PR111 PR120 PR124-PR127 PR130-PR132 PR135 PR136 PR144-PR146 PR148 PR150 PR151 PR157-PR159 PR161 PR165 PR166 PR168 PR174 PR179 PR180 PR187 PR188 PR192-PR203 PR205-PR208 PR211 PR216-PR220 PR224-PR227 PR235 PR236 PR241-PR243 PR247-PR249 PR251 PR255-PR257 PR259 PR262 PR266 PR267 PR269 PR272-PR274 PR280 PR286-PR290 PR292 PR293 PR295-PR300 PR302-PR304 PR309 PR310 PR326 PR330 PR331 PR340-PR342 PR344 PR346 PR6120-PR6122 PR6124 PR6279-PR6281 PR6284 PR6290 R3-R10 R12 R13 R17-R27 R29-R36 R38-R65 R68-R71 R73-R96 R98-R111 R113-R118 R120-R132 R134 R137-R140 R142 R143 R145 R148 R152-R156 R158 R160-R162 R164-R167 R169 R172 R174 R176-R178 R190 R195 R196 R199-R202 R204-R209 R211 R213-R220 R222 R223 R225-R228 R230-R232 R234 R238 R239 R241-R245 R249 R250 R253-R257 R259-R261 R263-R268 R270 R273-R277 R279-R288 R290 R292-R301 R303-R306 R308-R317 R319-R326 R330-R335 R343 R344 R346 R347 R349-R352 R354 R356-R360 R364-R366 R368-R370 R372-R380 R382 R383 R389 R390 R393-R401 R403 R405 R407 R409 R410 R415-R418 R420-R424 R426-R433 R435 R436 R439-R441 R443-R453 R455-R467 R469 R471-R473 R478 R481 R485-R516 R518-R538 R540-R544 R546 R548 R552-R555 R558 R559 R561-R564 R566 R568-R570 R572-R578 R580 R582 R585-R636 R639 R641-R646 R648-R651 R654 R658 R660 R667 R669 R671 R674 R675 R678-R682 R684-R687 R689 R691 R692 R694 R695 R697-R699 R701-R722 R724 R726-R741 R743 R744 R746 R748 R751 R753-R758 R761 R762 R764-R772 R774-R778 R780-R788 R790-R792 R795-R797 = RC0402
D7 = SOT323_213-2_1-1_3-2N7002W
D12 = DSMV
D21 D22 D33 = D-SOD523-1_2X0_8-0_65H
HOLE1 = H-TC315BC354D217P2
HOLE2 HOLE12 HOLE18 HOLE19 = H-TC315BC354D134P2
HOLE3 HOLE6 HOLE7 = H-TC256IC201BC236D161P2
HOLE4 = O-ZRTA-4
HOLE5 = H-ZRW-1
HOLE8 = H-O112X120D112X120N
HOLE9 = O-ZRTA-2
HOLE10 = H-O152X93D152X93N
HOLE11 = O-ZRTA-3
HOLE13 = O-ZRZ-7
HOLE14 = H-O138X114D138X114N
HOLE15 = O-ZRZ-8
HOLE16 = H-C118D118
HOLE17 = O-ZRTA-5
HOLE20 = H-C236IC180D140P2
HOLE21 = H-C236D140P2
HOLE22 = H-C236D142P2
HOLE23 = H-C256D134P2
J1 = JOPEN25X30_S
JDIM1 = DDR-DDRRK-20401-TP5B-204P-RUV
JDIM2 = DDR-DDRSK-20401-TP4B-204P-SMT
JP16 = RC3720-SMT
L16 PR137-PR139 PR153 PR164 PR338 PR339 PR6275 R97 R221 R237 R247 R248 R672 R673 R793 R794 = RC0805
L19 PR53-PR56 PR69 PR99 PR149 PR154 PR173 PR185 PR223 PR230-PR232 PR258 PR6125 PR6130 PR6285 R11 R16 R112 R135 R179 R180 R182 R185-R188 R192 R193 R198 R212 R240 R252 R302 R318 R327 R338 R362 R367 R388 R391 R404 R406 R414 R419 R434 R550 R637 R700 R745 R752 = SHORT0603
LED1 LED2 = LEDLTST-S326KGJRKT-3P-SMT
MR1 = SOT23_123-2_8-1_9
PC138 PC185 PC210 PC212 PC275 PC6212 PC6224 PC6227 PC6229 = ECAP6_3X6_1-7_2
PD3 = D-DO-214AC
PD8 = D-TO277_213-6_1X4_3
PD6004 PD6008 PQ6 PQ11 PQ13 PQ35 Q4 Q6 Q12 Q19 Q27 Q35 = UMT_213-3-1_3
PJ1 = 50458-00801-V02-8P-L
PJ2 = 20288-04XX-4P-L
PL1 PL9 PL11 PL13-PL15 PL6012 PL6013 = CHOKE-PCMC063T-3R3MN-SMT
PL2-PL5 = CHOKE-PCMC063T-R82MN-4P-SMT
PL6 PL16 = L3_2X2_5-1_55
PL7 PL8 = CHOKE-ETQP4LR36AFM
PQ1 PQ22 PQ24 PQ25 PQ27 PQ29 = SO-8FL-5P-OA
PQ2-PQ5 PQ7-PQ10 PQ12 PQ14-PQ17 PQ19 PQ23 PQ33 PQ36 PQ37 PQ39 PQ40 PQ6057-PQ6060 Q1 Q5 Q7-Q11 Q14-Q18 Q20-Q22 Q24-Q26 Q28-Q31 Q36 Q38-Q42 = SOT23_213-3_3-2
PQ18 PQ20 PQ21 PQ26 PQ31 PQ32 PQ34 PQ38 PQ6053-PQ6056 = WDFN5-3_05X3_05-65
PQ30 = POWER-5X6-1_27-7P
PR5 = RC1206
PR169 PR213 = RC3216
PR212 R14 R15 R28 R246 R339 R657 = SHORT0805
PU1 = QFN40-5X5-4-41P-ISL62771HRTZ-T
PU3 = QFN20-3X3-4-21P-0_8H
PU4 U12 = SOIC8-6-1_27
PU5 = QFN28-4X4-4-38P
PU6-PU9 = POWER-3_5X5-5-14P
PU10 PU19 Q34 = TSOP6-2_8-95
PU11 = QFN14-3X3-4-16P
PU12 = SON10-3X3-5-16P
PU14 = QFN13-2X3-5
PU15 PU6010 = QFN20-3X3-4-26P
PU16 = DFN10-3X3-5-11P-RT9296
Q2 Q3 Q13 Q23 Q32 Q37 Q43 Q56 = SC70-2_1-65-6P
RP1 = 10P8R
SPAD1-SPAD12 = SPAD-ZRZ-1NP
SW1 SW2 = SW-TME-533B-Q-TR-6P
TP2-TP5 TP8-TP11 TP45-TP61 = TP2050
TP6 TP7 TP15 TP16 TP18 TP19 TP21 TP23 TP24 TP29-TP31 TP33 TP63 TP66-TP68 TP74 TP76 TP78 TP84 TP88 TP95 = TP2675
TP12 TP14 TP17 TP20 TP22 TP25-TP28 TP34-TP43 TP62 TP64 TP65 TP73 TP75 TP77 TP86 TP87 TP89-TP94 = TP2650
U1 = SOT23-2_8-95-6P
U2-U5 U28 U29 U31 U32 = BGA96-HYNIX-H5TQ1G63AFP
U6 U33 U43 = SOT353-1-2_125-65-5P
U7-U10 U14 U37 U40 U47-U50 = SSOP5-P-A-TOSHIBA-B
U13 = QFN40-5X5-4-41P-IT6515FN
U15 = QFN32-4X4-4-33P-0_9H
U16 U17 = MIC-FM-M201-U03-6P
U18 = QFN40-5X5-4-50P-0_75H
U19 = SENSOR-3X3-5-16P-SMT
U20 U25 U46 = SOT23-5
U21 U24 = ESD10-4_1X2-8-11P
U22 = QFN16-3X3-5-17P-TPS2543RTER
U23 = QFN48-6X6-4-49P-ALC280
U26 = QFN24-4X4-5-25P-ALC5629
U34 = BGA595-NVIDIA-N13P-GV2-S-A2
U35 = BGA1356-INTEL-SKYLAKE-U
U36 U38 = SLP10-2_5X1-5-10P
U39 = SOIC8-7_9-1_27
U41 = SOIC8-8-1_27
U42 = TRF-N1010G-25P
U44 = TSSOP28-6_4-65-SLB9635TT
U45 = LQFP128-16X16-4-1_6H
Y1 Y3 = XTL-3_2X2_5-2_2X1_7
Y2 = XTL-3_2X1_5-2_5-0_8H
Y4 = XTL-3_2X2_5-2_2X1_7-4P

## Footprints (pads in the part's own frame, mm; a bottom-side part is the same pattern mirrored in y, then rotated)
8P4R
  rect 0.406x1.092 smd: 1(-1.194,-0.8) 2(-1.194,0.8) 3(-0.406,-0.8) 4(-0.406,0.8) 5(0.406,-0.8) 6(0.406,0.8) 7(1.194,-0.8) 8(1.194,0.8)
10P8R
  rect 0.305x1.092 smd: 1(-1.27,-0.85) 2(-0.635,-0.85) 3(0,-0.85) 4(0.635,-0.85) 5(1.27,-0.85) 6(1.27,0.85) 7(0.635,0.85) 8(0,0.85) 9(-0.635,0.85) 10(-1.27,0.85)
20288-04XX-4P-L
  round 1.295 hole 0.889: 1(-3.75,0) 2(-1.25,0) 3(1.25,0) 4(3.75,0)
50224-00401-001-4P-L
  rect 0.61x1.549 smd: 1(-1.5,2) 2(-0.5,2) 3(0.5,2) 4(1.5,2)
  rect 1.194x1.803 smd: 5(-2.8,-1.875) 6(2.8,-1.875)
50458-00801-V02-8P-L
  rect 0.559x1.295 smd: 1(-7,5.025) 2(-5,5.025) 3(-3,5.025) 4(-1,5.025) 5(1,5.025) 6(3,5.025) 7(5,5.025) 8(7,5.025)
  rect 1.295x2.057 smd: 9(-10.1,0) 10(10.1,0)
50503-0040N-V01-4P-L
  rect 0.508x1.295 smd: 1(-1.5,2.8) 2(-0.5,2.8) 3(0.5,2.8) 4(1.5,2.8)
  rect 1.803x1.397 smd: 5(-3.65,0) 6(3.65,0)
50584-0280N-V01-28P-L
  rect 0.61x1.092 smd: 1(-13.5,2.05) 2(-12.5,2.05) 3(-11.5,2.05) 4(-10.5,2.05) 5(-9.5,2.05) 6(-8.5,2.05) 7(-7.5,2.05) 8(-6.5,2.05) 9(-5.5,2.05) 10(-4.5,2.05) 11(-3.5,2.05) 12(-2.5,2.05) 13(-1.5,2.05) 14(-0.5,2.05) 15(0.5,2.05) 16(1.5,2.05) 17(2.5,2.05) 18(3.5,2.05) 19(4.5,2.05) 20(5.5,2.05) 21(6.5,2.05) 22(7.5,2.05) 23(8.5,2.05) 24(9.5,2.05) 25(10.5,2.05) 26(11.5,2.05) 27(12.5,2.05) 28(13.5,2.05)
  rect 2.159x2.997 smd: 29(-15.975,0) 30(15.975,0)
88511-10XX-10P-L
  rect 0.305x1.295 smd: 1(-2.25,2.8) 2(-1.75,2.8) 3(-1.25,2.8) 4(-0.75,2.8) 5(-0.25,2.8) 6(0.25,2.8) 7(0.75,2.8) 8(1.25,2.8) 9(1.75,2.8) 10(2.25,2.8)
  rect 1.803x1.397 smd: 11(-3.9,0) 12(3.9,0)
88511-180N-18P-L
  rect 0.305x1.295 smd: 1(-4.25,2.8) 2(-3.75,2.8) 3(-3.25,2.8) 4(-2.75,2.8) 5(-2.25,2.8) 6(-1.75,2.8) 7(-1.25,2.8) 8(-0.75,2.8) 9(-0.25,2.8) 10(0.25,2.8) 11(0.75,2.8) 12(1.25,2.8) 13(1.75,2.8) 14(2.25,2.8) 15(2.75,2.8) 16(3.25,2.8) 17(3.75,2.8) 18(4.25,2.8)
  rect 1.803x1.397 smd: 19(-5.9,0) 20(5.9,0)
88513-0601-6P-L-SMT
  rect 0.508x1.6 smd: 1(-2.5,2.95) 2(-1.5,2.95) 3(-0.5,2.95) 4(0.5,2.95) 5(1.5,2.95) 6(2.5,2.95)
  rect 1.803x1.397 smd: 7(-4.65,0) 8(4.65,0)
88513-0801-8P-L
  rect 0.508x1.295 smd: 1(-3.5,0) 2(-2.5,0) 3(-1.5,0) 4(-0.5,0) 5(0.5,0) 6(1.5,0) 7(2.5,0) 8(3.5,0)
  rect 1.803x1.397 smd: 9(-5.65,-2.8) 10(5.65,-2.8)
BAT-AP-AAA-BAT-054-K01-2P-SMT
  round 0.991 hole 0.991 unplated: (0,-8)
  round 1.397 hole 1.397 unplated: (0,8)
  rect 3.505x3.988 smd: 1(15.25,0) 2(-16.35,0)
BGA96-HYNIX-H5TQ1G63AFP
  round 0.356 smd: A1(-6,-3.2) A2(-6,-2.4) A3(-6,-1.6) A7(-6,1.6) A8(-6,2.4) A9(-6,3.2) B1(-5.2,-3.2) B2(-5.2,-2.4) B3(-5.2,-1.6) B7(-5.2,1.6) B8(-5.2,2.4) B9(-5.2,3.2) C1(-4.4,-3.2) C2(-4.4,-2.4) C3(-4.4,-1.6) C7(-4.4,1.6) C8(-4.4,2.4) C9(-4.4,3.2) D1(-3.6,-3.2) D2(-3.6,-2.4) D3(-3.6,-1.6) D7(-3.6,1.6) D8(-3.6,2.4) D9(-3.6,3.2) E1(-2.8,-3.2) E2(-2.8,-2.4) E3(-2.8,-1.6) E7(-2.8,1.6) E8(-2.8,2.4) E9(-2.8,3.2) F1(-2,-3.2) F2(-2,-2.4) F3(-2,-1.6) F7(-2,1.6) F8(-2,2.4) F9(-2,3.2) G1(-1.2,-3.2) G2(-1.2,-2.4) G3(-1.2,-1.6) G7(-1.2,1.6) G8(-1.2,2.4) G9(-1.2,3.2) H1(-0.4,-3.2) H2(-0.4,-2.4) H3(-0.4,-1.6) H7(-0.4,1.6) H8(-0.4,2.4) H9(-0.4,3.2) J1(0.4,-3.2) J2(0.4,-2.4) J3(0.4,-1.6) J7(0.4,1.6) J8(0.4,2.4) J9(0.4,3.2) K1(1.2,-3.2) K2(1.2,-2.4) K3(1.2,-1.6) K7(1.2,1.6) K8(1.2,2.4) K9(1.2,3.2) L1(2,-3.2) L2(2,-2.4) L3(2,-1.6) L7(2,1.6) L8(2,2.4) L9(2,3.2) M1(2.8,-3.2) M2(2.8,-2.4) M3(2.8,-1.6) M7(2.8,1.6) M8(2.8,2.4) M9(2.8,3.2) N1(3.6,-3.2) N2(3.6,-2.4) N3(3.6,-1.6) N7(3.6,1.6) N8(3.6,2.4) N9(3.6,3.2) P1(4.4,-3.2) P2(4.4,-2.4) P3(4.4,-1.6) P7(4.4,1.6) P8(4.4,2.4) P9(4.4,3.2) R1(5.2,-3.2) R2(5.2,-2.4) R3(5.2,-1.6) R7(5.2,1.6) R8(5.2,2.4) R9(5.2,3.2) T1(6,-3.2) T2(6,-2.4) T3(6,-1.6) T7(6,1.6) T8(6,2.4) T9(6,3.2)
BGA595-NVIDIA-N13P-GV2-S-A2
  round 0.381 smd: A2(-10.7,-9.9) A3(-10.7,-9.1) A4(-10.7,-8.3) A6(-10.7,-6.6) A7(-10.7,-5.8) A9(-10.7,-4.12) A10(-10.7,-3.32) A12(-10.7,-1.64) A13(-10.7,-0.84) A15(-10.7,0.84) A16(-10.7,1.64) A18(-10.7,3.32) A19(-10.7,4.12) A21(-10.7,5.8) A22(-10.7,6.6) A24(-10.7,8.3) A25(-10.7,9.1) A26(-10.7,9.9) AA1(5.8,-10.7) AA2(5.8,-9.9) AA3(5.8,-9.1) AA4(5.8,-8.3) AA5(5.8,-7.5) AA6(5.8,-6.66) AA7(5.8,-5.8) AA8(5.8,-4.96) AA9(5.86,-4.12) AA10(5.86,-3.32) AA12(5.86,-1.64) AA13(5.86,-0.84) AA14(5.86,0) AA15(5.86,0.84) AA16(5.86,1.64) AA18(5.86,3.32) AA19(5.86,4.12) AA20(5.8,4.96) AA21(5.8,5.8) AA22(5.8,6.66) AA23(5.8,7.5) AA24(5.8,8.3) AA25(5.8,9.1) AA26(5.8,9.9) AA27(5.8,10.7) AB1(6.6,-10.7) AB2(6.6,-9.9) AB3(6.6,-9.1) AB4(6.6,-8.3) AB5(6.6,-7.5) AB6(6.6,-6.6) AB7(6.66,-5.8) AB8(6.66,-4.96) AB9(6.66,-4.12) AB10(6.66,-3.32) AB11(6.66,-2.48) AB12(6.66,-1.64) AB13(6.66,-0.84) AB14(6.66,0) AB15(6.66,0.84) AB16(6.66,1.64) AB17(6.66,2.48) AB18(6.66,3.32) AB19(6.66,4.12) AB20(6.66,4.96) AB21(6.66,5.8) AB22(6.6,6.6) AB23(6.6,7.5) AB24(6.6,8.3) AB25(6.6,9.1) AB26(6.6,9.9) AB27(6.6,10.7) AC2(7.45,-9.9) AC3(7.45,-9.1) AC4(7.45,-8.3) AC5(7.45,-7.45) AC6(7.5,-6.6) AC7(7.5,-5.8) AC8(7.5,-4.96) AC9(7.5,-4.12) AC10(7.5,-3.32) AC11(7.5,-2.48) AC12(7.5,-1.64) AC13(7.5,-0.84) AC14(7.5,0) AC15(7.5,0.84) AC16(7.5,1.64) AC17(7.5,2.48) AC18(7.5,3.32) AC19(7.5,4.12) AC20(7.5,4.96) AC21(7.5,5.8) AC22(7.5,6.6) AC23(7.45,7.45) AC24(7.45,8.3) AC25(7.45,9.1) AC26(7.45,9.9) AD1(8.3,-10.7) AD2(8.3,-9.9) AD3(8.3,-9.1) AD4(8.3,-8.3) AD5(8.3,-7.45) AD6(8.3,-6.6) AD7(8.3,-5.8) AD8(8.3,-4.96) AD9(8.3,-4.12) AD10(8.3,-3.32) AD11(8.3,-2.48) AD12(8.3,-1.64) AD13(8.3,-0.84) AD14(8.3,0) AD15(8.3,0.84) AD16(8.3,1.64) AD17(8.3,2.48) AD18(8.3,3.32) AD19(8.3,4.12) AD20(8.3,4.96) AD21(8.3,5.8) AD22(8.3,6.6) AD23(8.3,7.45) AD24(8.3,8.3) AD25(8.3,9.1) AD26(8.3,9.9) AD27(8.3,10.7) AE1(9.1,-10.7) AE2(9.1,-9.9) AE3(9.1,-9.1) AE4(9.1,-8.3) AE5(9.1,-7.45) AE6(9.1,-6.6) AE7(9.1,-5.8) AE8(9.1,-4.96) AE9(9.1,-4.12) AE10(9.1,-3.32) AE11(9.1,-2.48) AE12(9.1,-1.64) AE13(9.1,-0.84) AE14(9.1,0) AE15(9.1,0.84) AE16(9.1,1.64) AE17(9.1,2.48) AE18(9.1,3.32) AE19(9.1,4.12) AE20(9.1,4.96) AE21(9.1,5.8) AE22(9.1,6.6) AE23(9.1,7.45) AE24(9.1,8.3) AE25(9.1,9.1) AE26(9.1,9.9) AE27(9.1,10.7) AF1(9.9,-10.7) AF2(9.9,-9.9) AF3(9.9,-9.1) AF4(9.9,-8.3) AF5(9.9,-7.45) AF6(9.9,-6.6) AF7(9.9,-5.8) AF8(9.9,-4.96) AF9(9.9,-4.12) AF10(9.9,-3.32) AF11(9.9,-2.48) AF12(9.9,-1.64) AF13(9.9,-0.84) AF14(9.9,0) AF15(9.9,0.84) AF16(9.9,1.64) AF17(9.9,2.48) AF18(9.9,3.32) AF19(9.9,4.12) AF20(9.9,4.96) AF21(9.9,5.8) AF22(9.9,6.6) AF23(9.9,7.45) AF24(9.9,8.3) AF25(9.9,9.1) AF26(9.9,9.9) AF27(9.9,10.7) AG2(10.7,-9.9) AG3(10.7,-9.1) AG4(10.7,-8.3) AG6(10.7,-6.6) AG7(10.7,-5.8) AG9(10.7,-4.12) AG10(10.7,-3.32) AG12(10.7,-1.64) AG13(10.7,-0.84) AG15(10.7,0.84) AG16(10.7,1.64) AG18(10.7,3.32) AG19(10.7,4.12) AG21(10.7,5.8) AG22(10.7,6.6) AG24(10.7,8.3) AG25(10.7,9.1) AG26(10.7,9.9) B1(-9.9,-10.7) B2(-9.9,-9.9) B3(-9.9,-9.1) B4(-9.9,-8.3) B5(-9.9,-7.45) B6(-9.9,-6.6) B7(-9.9,-5.8) B8(-9.9,-4.96) B9(-9.9,-4.12) B10(-9.9,-3.32) B11(-9.9,-2.48) B12(-9.9,-1.64) B13(-9.9,-0.84) B14(-9.9,0) B15(-9.9,0.84) B16(-9.9,1.64) B17(-9.9,2.48) B18(-9.9,3.32) B19(-9.9,4.12) B20(-9.9,4.96) B21(-9.9,5.8) B22(-9.9,6.6) B23(-9.9,7.45) B24(-9.9,8.3) B25(-9.9,9.1) B26(-9.9,9.9) B27(-9.9,10.7) C1(-9.1,-10.7) C2(-9.1,-9.9) C3(-9.1,-9.1) C4(-9.1,-8.3) C5(-9.1,-7.45) C6(-9.1,-6.6) C7(-9.1,-5.8) C8(-9.1,-4.96) C9(-9.1,-4.12) C10(-9.1,-3.32) C11(-9.1,-2.48) C12(-9.1,-1.64) C13(-9.1,-0.84) C14(-9.1,0) C15(-9.1,0.84) C16(-9.1,1.64) C17(-9.1,2.48) C18(-9.1,3.32) C19(-9.1,4.12) C20(-9.1,4.96) C21(-9.1,5.8) C22(-9.1,6.6) C23(-9.1,7.45) C24(-9.1,8.3) C25(-9.1,9.1) C26(-9.1,9.9) C27(-9.1,10.7) D1(-8.3,-10.7) D2(-8.3,-9.9) D3(-8.3,-9.1) D4(-8.3,-8.3) D5(-8.3,-7.45) D6(-8.3,-6.6) D7(-8.3,-5.8) D8(-8.3,-4.96) D9(-8.3,-4.12) D10(-8.3,-3.32) D11(-8.3,-2.48) D12(-8.3,-1.64) D13(-8.3,-0.84) D14(-8.3,0) D15(-8.3,0.84) D16(-8.3,1.64) D17(-8.3,2.48) D18(-8.3,3.32) D19(-8.3,4.12) D20(-8.3,4.96) D21(-8.3,5.8) D22(-8.3,6.6) D23(-8.3,7.45) D24(-8.3,8.3) D25(-8.3,9.1) D26(-8.3,9.9) D27(-8.3,10.7) E2(-7.45,-9.9) E3(-7.45,-9.1) E4(-7.45,-8.3) E5(-7.45,-7.45) E6(-7.5,-6.6) E7(-7.5,-5.8) E8(-7.5,-4.96) E9(-7.5,-4.12) E10(-7.5,-3.32) E11(-7.5,-2.48) E12(-7.5,-1.64) E13(-7.5,-0.84) E14(-7.5,0) E15(-7.5,0.84) E16(-7.5,1.64) E17(-7.5,2.48) E18(-7.5,3.32) E19(-7.5,4.12) E20(-7.5,4.96) E21(-7.5,5.8) E22(-7.5,6.6) E23(-7.45,7.45) E24(-7.45,8.3) E25(-7.45,9.1) E26(-7.45,9.9) F1(-6.6,-10.7) F2(-6.6,-9.9) F3(-6.6,-9.1) F4(-6.6,-8.3) F5(-6.6,-7.5) F6(-6.6,-6.6) F7(-6.66,-5.8) F8(-6.66,-4.96) F9(-6.66,-4.12) F10(-6.66,-3.32) F11(-6.66,-2.48) F12(-6.66,-1.64) F13(-6.66,-0.84) F14(-6.66,0) F15(-6.66,0.84) F16(-6.66,1.64) F17(-6.66,2.48) F18(-6.66,3.32) F19(-6.66,4.12) F20(-6.66,4.96) F21(-6.66,5.8) F22(-6.6,6.6) F23(-6.6,7.5) F24(-6.6,8.3) F25(-6.6,9.1) F26(-6.6,9.9) F27(-6.6,10.7) G1(-5.8,-10.7) G2(-5.8,-9.9) G3(-5.8,-9.1) G4(-5.8,-8.3) G5(-5.8,-7.5) G6(-5.8,-6.66) G7(-5.8,-5.8) G8(-5.8,-4.96) G9(-5.86,-4.12) G10(-5.86,-3.32) G12(-5.86,-1.64) G13(-5.86,-0.84) G14(-5.86,0) G15(-5.86,0.84) G16(-5.86,1.64) G18(-5.86,3.32) G19(-5.86,4.12) G20(-5.8,4.96) G21(-5.8,5.8) G22(-5.8,6.66) G23(-5.8,7.5) G24(-5.8,8.3) G25(-5.8,9.1) G26(-5.8,9.9) G27(-5.8,10.7) H2(-4.96,-9.9) H3(-4.96,-9.1) H4(-4.96,-8.3) H5(-4.96,-7.5) H6(-4.96,-6.66) H22(-4.96,6.66) H23(-4.96,7.5) H24(-4.96,8.3) H25(-4.96,9.1) H26(-4.96,9.9) J1(-4.12,-10.7) J2(-4.12,-9.9) J3(-4.12,-9.1) J4(-4.12,-8.3) J5(-4.12,-7.5) J6(-4.12,-6.66) J7(-4.12,-5.86) J21(-4.12,5.86) J22(-4.12,6.66) J23(-4.12,7.5) J24(-4.12,8.3) J25(-4.12,9.1) J26(-4.12,9.9) J27(-4.12,10.7) K1(-3.32,-10.7) K2(-3.32,-9.9) K3(-3.32,-9.1) K4(-3.32,-8.3) K5(-3.32,-7.5) K6(-3.32,-6.66) K7(-3.32,-5.86) K21(-3.32,5.86) K22(-3.32,6.66) K23(-3.32,7.5) K24(-3.32,8.3) K25(-3.32,9.1) K26(-3.32,9.9) K27(-3.32,10.7) L2(-2.48,-9.9) L3(-2.48,-9.1) L4(-2.48,-8.3) L5(-2.48,-7.5) L6(-2.48,-6.66) L22(-2.48,6.66) L23(-2.48,7.5) L24(-2.48,8.3) L25(-2.48,9.1) L26(-2.48,9.9) M1(-1.64,-10.7) M2(-1.64,-9.9) M3(-1.64,-9.1) M4(-1.64,-8.3) M5(-1.64,-7.5) M6(-1.64,-6.66) M7(-1.64,-5.86) M21(-1.64,5.86) M22(-1.64,6.66) M23(-1.64,7.5) M24(-1.64,8.3) M25(-1.64,9.1) M26(-1.64,9.9) M27(-1.64,10.7) N1(-0.84,-10.7) N2(-0.84,-9.9) N3(-0.84,-9.1) N4(-0.84,-8.3) N5(-0.84,-7.5) N6(-0.84,-6.66) N7(-0.84,-5.86) N21(-0.84,5.86) N22(-0.84,6.66) N23(-0.84,7.5) N24(-0.84,8.3) N25(-0.84,9.1) N26(-0.84,9.9) N27(-0.84,10.7) P2(0,-9.9) P3(0,-9.1) P4(0,-8.3) P5(0,-7.5) P6(0,-6.66) P22(0,6.66) P23(0,7.5) P24(0,8.3) P25(0,9.1) P26(0,9.9) R1(0.84,-10.7) R2(0.84,-9.9) R3(0.84,-9.1) R4(0.84,-8.3) R5(0.84,-7.5) R6(0.84,-6.66) R7(0.84,-5.86) R21(0.84,5.86) R22(0.84,6.66) R23(0.84,7.5) R24(0.84,8.3) R25(0.84,9.1) R26(0.84,9.9) R27(0.84,10.7) T1(1.64,-10.7) T2(1.64,-9.9) T3(1.64,-9.1) T4(1.64,-8.3) T5(1.64,-7.5) T6(1.64,-6.66) T7(1.64,-5.86) T21(1.64,5.86) T22(1.64,6.66) T23(1.64,7.5) T24(1.64,8.3) T25(1.64,9.1) T26(1.64,9.9) T27(1.64,10.7) U2(2.48,-9.9) U3(2.48,-9.1) U4(2.48,-8.3) U5(2.48,-7.5) U6(2.48,-6.66) U22(2.48,6.66) U23(2.48,7.5) U24(2.48,8.3) U25(2.48,9.1) U26(2.48,9.9) V1(3.32,-10.7) V2(3.32,-9.9) V3(3.32,-9.1) V4(3.32,-8.3) V5(3.32,-7.5) V6(3.32,-6.66) V7(3.32,-5.86) V21(3.32,5.86) V22(3.32,6.66) V23(3.32,7.5) V24(3.32,8.3) V25(3.32,9.1) V26(3.32,9.9) V27(3.32,10.7) W1(4.12,-10.7) W2(4.12,-9.9) W3(4.12,-9.1) W4(4.12,-8.3) W5(4.12,-7.5) W6(4.12,-6.66) W7(4.12,-5.86) W21(4.12,5.86) W22(4.12,6.66) W23(4.12,7.5) W24(4.12,8.3) W25(4.12,9.1) W26(4.12,9.9) W27(4.12,10.7) Y2(4.96,-9.9) Y3(4.96,-9.1) Y4(4.96,-8.3) Y5(4.96,-7.5) Y6(4.96,-6.66) Y22(4.96,6.66) Y23(4.96,7.5) Y24(4.96,8.3) Y25(4.96,9.1) Y26(4.96,9.9)
  round 0.4 smd: K10(-4,-4) K11(-4,-3) K12(-4,-2) K13(-4,-1) K14(-4,0) K15(-4,1) K16(-4,2) K17(-4,3) K18(-4,4) L10(-3,-4) L11(-3,-3) L12(-3,-2) L13(-3,-1) L14(-3,0) L15(-3,1) L16(-3,2) L17(-3,3) L18(-3,4) M10(-2,-4) M11(-2,-3) M12(-2,-2) M13(-2,-1) M14(-2,0) M15(-2,1) M16(-2,2) M17(-2,3) M18(-2,4) N10(-1,-4) N11(-1,-3) N12(-1,-2) N13(-1,-1) N14(-1,0) N15(-1,1) N16(-1,2) N17(-1,3) N18(-1,4) P10(0,-4) P11(0,-3) P12(0,-2) P13(0,-1) P14(0,0) P15(0,1) P16(0,2) P17(0,3) P18(0,4) R10(1,-4) R11(1,-3) R12(1,-2) R13(1,-1) R14(1,0) R15(1,1) R16(1,2) R17(1,3) R18(1,4) T10(2,-4) T11(2,-3) T12(2,-2) T13(2,-1) T14(2,0) T15(2,1) T16(2,2) T17(2,3) T18(2,4) U10(3,-4) U11(3,-3) U12(3,-2) U13(3,-1) U14(3,0) U15(3,1) U16(3,2) U17(3,3) U18(3,4) V10(4,-4) V11(4,-3) V12(4,-2) V13(4,-1) V14(4,0) V15(4,1) V16(4,2) V17(4,3) V18(4,4)
